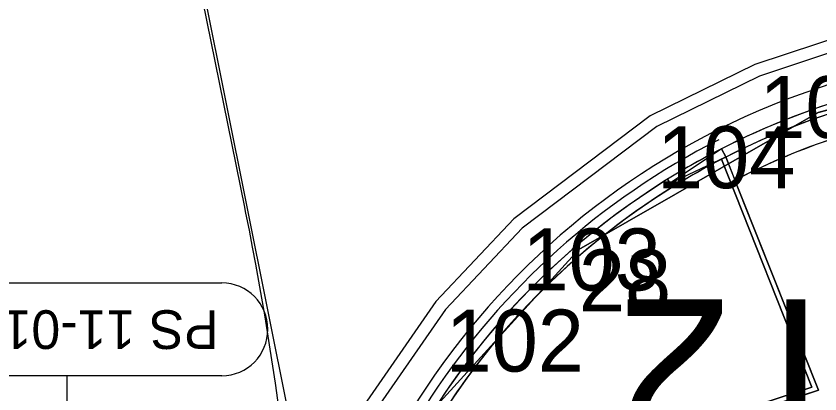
# Model space of a CAD drawing. Extents: x -728800 to -728100, y -1073200 to -1072700.
# Drawn here: x -728506.62 to -728493.65, y -1073032.48 to -1073026.38 of the extents above; entities that cross this region are included whole.
import ezdxf

# ---------------------------------------------------------------- set-up
doc = ezdxf.new("R2010")
doc.units = 0
for name, color, linetype in [('_NOR-návrh tenká', 7, 'Continuous'), ('_NOR-VDZ', 7, 'Continuous'), ('_NOR-šraf_+-0', 7, 'Continuous'), ('_NOR-šraf_+12', 7, 'Continuous'), ('_NOR-šraf_bezbariéra', 7, 'Continuous'), ('_NOR-šraf_chodník', 7, 'Continuous'), ('_NOR-šraf_varovný pás', 7, 'Continuous'), ('_NOR-šraf_vozovka', 7, 'Continuous'), ('_NOR-šraf_zeleň', 7, 'Continuous'), ('A1_OBVOD Spravy železnic', 7, 'Continuous'), ('A2_OBVOD STAVBY', 7, 'Continuous'), ('B1_body_poloha', 7, 'Continuous'), ('B2_body_číslo', 7, 'Continuous'), ('K_01_Hranice parcel', 7, 'Continuous'), ('KTA_členění PS a SO', 7, 'Continuous'), ('ZA_01_Trvalý_pro_SŽDC_dle_UMVZST', 7, 'Continuous'), ('ZA_02_Dočasný_do_1_roku', 7, 'Continuous')]:
    doc.layers.add(name, color=color, linetype=linetype)

msp = doc.modelspace()

# ---------------------------------------------------------------- linework, layer by layer
at = {"layer": '_NOR-návrh tenká'}
for p, q in [((-728495.239, -1073028.523), (-728496.07, -1073029.079)), ((-728495.171, -1073028.656), (-728495.239, -1073028.523)), ((-728496.07, -1073029.079), (-728495.171, -1073028.656)), ((-728496.11, -1073029.015), (-728496.031, -1073029.142))]:
    msp.add_line(p, q, dxfattribs=at)
for points in [[(-728495.168, -1073028.664), (-728493.678, -1073032.423), (-728500.748, -1073034.736)], [(-728495.242, -1073028.693), (-728493.784, -1073032.373), (-728500.708, -1073034.638)]]:
    msp.add_lwpolyline(points, dxfattribs=at)
for radius, end in [(12.3, 176.1779), (12, 176.2645), (11.85, 176.3095), (11.45, 117.2893)]:
    msp.add_arc((-728489.773, -1073039.206), radius, 105.42, end, dxfattribs=at)
at = {"layer": '_NOR-VDZ'}
msp.add_lwpolyline([(-728502.909, -1073029.566), (-728502.929, -1073029.468), (-728506.181, -1073013.442)], dxfattribs=at)
for centre, radius, start, end in [((-728489.773, -1073039.206), 12.15, 116.9619, 176.2207), ((-728551.773, -1073039.431), 49.85, 1.1854, 11.4145)]:
    msp.add_arc(centre, radius, start, end, dxfattribs=at)
at = {"layer": '_NOR-šraf_+-0'}
for points in [[(-728495.171, -1073028.656), (-728495.023, -1073029.03), (-728493.678, -1073032.423), (-728500.748, -1073034.736)], [(-728500.708, -1073034.638), (-728493.784, -1073032.373), (-728495.242, -1073028.693)]]:
    msp.add_lwpolyline(points, dxfattribs=at)
msp.add_arc((-728489.773, -1073039.206), 11.85, 117.0974, 117.4861, dxfattribs=at)
at = {"layer": '_NOR-šraf_+12'}
for p, q in [((-728496.07, -1073029.079), (-728496.11, -1073029.015)), ((-728496.031, -1073029.142), (-728496.07, -1073029.079))]:
    msp.add_line(p, q, dxfattribs=at)
for radius, end in [(12, 176.2645), (11.85, 176.3095)]:
    msp.add_arc((-728489.773, -1073039.206), radius, 121.8734, end, dxfattribs=at)
at = {"layer": '_NOR-šraf_bezbariéra'}
msp.add_lwpolyline([(-728495.239, -1073028.523), (-728495.171, -1073028.656), (-728495.171, -1073028.656)], dxfattribs=at)
for radius in [12, 11.85]:
    msp.add_arc((-728489.773, -1073039.206), radius, 105.42, 117.0974, dxfattribs=at)
at = {"layer": '_NOR-šraf_chodník'}
for p, q in [((-728493.678, -1073032.423), (-728495.023, -1073029.03)), ((-728498.439, -1073033.98), (-728493.678, -1073032.423))]:
    msp.add_line(p, q, dxfattribs=at)
msp.add_arc((-728489.773, -1073039.206), 11.45, 109.1994, 117.2893, dxfattribs=at)
at = {"layer": '_NOR-šraf_varovný pás'}
msp.add_lwpolyline([(-728495.171, -1073028.656), (-728495.023, -1073029.03), (-728495.023, -1073029.03)], dxfattribs=at)
for radius, start, end in [(11.85, 105.42, 117.0974), (11.45, 109.1994, 117.2893)]:
    msp.add_arc((-728489.773, -1073039.206), radius, start, end, dxfattribs=at)
at = {"layer": '_NOR-šraf_vozovka'}
for radius, start, end in [(12.3, 105.42, 176.1779), (12, 105.42, 117.0974), (12, 117.0974, 121.8734), (12, 121.8734, 176.2645)]:
    msp.add_arc((-728489.773, -1073039.206), radius, start, end, dxfattribs=at)
at = {"layer": '_NOR-šraf_zeleň'}
msp.add_lwpolyline([(-728495.242, -1073028.693), (-728493.784, -1073032.373), (-728500.708, -1073034.638)], dxfattribs=at)
for start, end in [(117.4861, 121.8734), (121.8734, 157.3304)]:
    msp.add_arc((-728489.773, -1073039.206), 11.85, start, end, dxfattribs=at)
at = {"layer": 'A1_OBVOD Spravy železnic'}
msp.add_lwpolyline([(-728503.24, -1073052.34), (-728501.19, -1073037.94), (-728499.78, -1073032.61), (-728497.54, -1073030.15), (-728493.68, -1073027.94), (-728443.97, -1073014.59), (-728443.68, -1073014.51), (-728441.09, -1073023.23), (-728428.92, -1073019.94), (-728429.82, -1073016.43), (-728427.49, -1073015.84), (-728421.24, -1073014.23), (-728422.34, -1073010.27), (-728422.77, -1073008.34), (-728418.21, -1073007), (-728380.57, -1072997.2), (-728343.1, -1072987.57), (-728330.49, -1072984.52), (-728326.79, -1072988.95)], dxfattribs=at)
at = {"layer": 'A2_OBVOD STAVBY'}
msp.add_lwpolyline([(-728488.873, -1073026.674), (-728489.181, -1073025.557), (-728493.185, -1073026.66), (-728494.705, -1073027.164), (-728496.389, -1073027.993), (-728498.589, -1073029.657), (-728499.85, -1073030.989), (-728500.962, -1073032.598), (-728501.8, -1073034.243), (-728502.009, -1073034.876), (-728501.833, -1073035.753)], dxfattribs=at)
at = {"layer": 'B1_body_poloha'}
for p, q in [((-728494.63, -1073027.35), (-728494.63, -1073027.35)), ((-728493.68, -1073027.94), (-728493.68, -1073027.94)), ((-728496.28, -1073028.16), (-728496.28, -1073028.16)), ((-728498.45, -1073029.81), (-728498.45, -1073029.81)), ((-728497.54, -1073030.15), (-728497.54, -1073030.15)), ((-728499.69, -1073031.12), (-728499.69, -1073031.12))]:
    msp.add_line(p, q, dxfattribs=at)
at = {"layer": 'K_01_Hranice parcel'}
msp.add_line((-728501.19, -1073037.94), (-728506.11, -1073013.42), dxfattribs=at)
msp.add_lwpolyline([(-728443.97, -1073014.59), (-728493.68, -1073027.94), (-728497.54, -1073030.15), (-728499.78, -1073032.61)], dxfattribs=at)
at = {"layer": 'KTA_členění PS a SO'}
msp.add_line((-728505.8, -1073032.188), (-728505.8, -1073036.528), dxfattribs=at)
for points in [[(-728508.3, -1073030.688), (-728503.3, -1073030.688)], [(-728503.3, -1073032.188), (-728508.3, -1073032.188)]]:
    msp.add_lwpolyline(points, dxfattribs=at)
msp.add_arc((-728503.306, -1073031.438), 0.75, 270.4529, 89.5471, dxfattribs=at)
at = {"layer": 'ZA_01_Trvalý_pro_SŽDC_dle_UMVZST'}
msp.add_lwpolyline([(-728500.719, -1073036.161), (-728501.19, -1073037.94), (-728493.84, -1073039.37), (-728493.51, -1073034.35), (-728488.39, -1073034.38), (-728491.302, -1073027.301), (-728493.68, -1073027.94), (-728497.54, -1073030.15), (-728499.78, -1073032.61)], close=True, dxfattribs=at)
at = {"layer": 'ZA_02_Dočasný_do_1_roku'}
msp.add_lwpolyline([(-728493.127, -1073026.851), (-728494.629, -1073027.35), (-728496.284, -1073028.164), (-728498.455, -1073029.806), (-728499.694, -1073031.116), (-728500.79, -1073032.701), (-728501.615, -1073034.32), (-728501.802, -1073034.888), (-728501.559, -1073036.1), (-728500.719, -1073036.161), (-728499.78, -1073032.61), (-728497.54, -1073030.15), (-728493.68, -1073027.94), (-728491.302, -1073027.301)], dxfattribs=at)

# ---------------------------------------------------------------- texts
at = {"layer": 'B2_body_číslo'}
for s, p in [('105', (-728494.63, -1073028.35)), ('104', (-728496.28, -1073029.16)), ('103', (-728498.45, -1073030.81)), ('28', (-728497.54, -1073031.15)), ('102', (-728499.69, -1073032.12))]:
    msp.add_text(s, height=1, dxfattribs=at).set_placement(p)
at = {"layer": 'KTA_členění PS a SO'}
msp.add_text('PS 11-01-31', height=0.625, rotation=180, dxfattribs=at).set_placement((-728503.35, -1073031.13))
at = {"layer": 'ZA_01_Trvalý_pro_SŽDC_dle_UMVZST'}
msp.add_text('T2', height=2.5, rotation=180, dxfattribs=at).set_placement((-728493.022, -1073030.953))

doc.saveas('drawing.dxf')
